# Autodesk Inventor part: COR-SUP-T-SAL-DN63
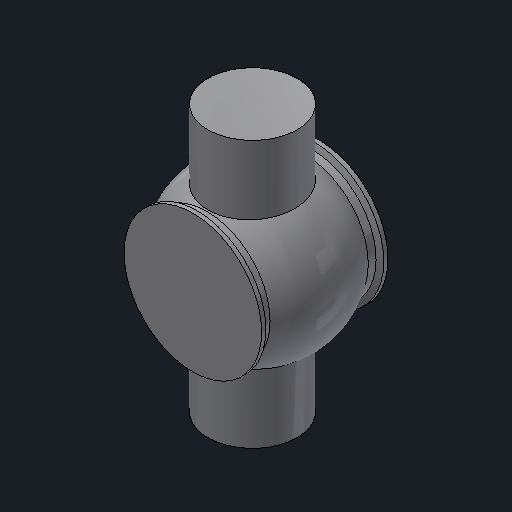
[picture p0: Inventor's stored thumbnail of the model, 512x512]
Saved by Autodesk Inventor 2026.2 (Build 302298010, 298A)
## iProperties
Created: 2026-03
Part Number: COR-SUP-T-SAL-DN63
Material: Generico
Document SubType Name: Modeling
Designer: marz-m
Density: 1 g/cm^3
Appearance: Default
Author: marz-m
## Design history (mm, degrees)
feature "Solido1"
node "Solido2"
